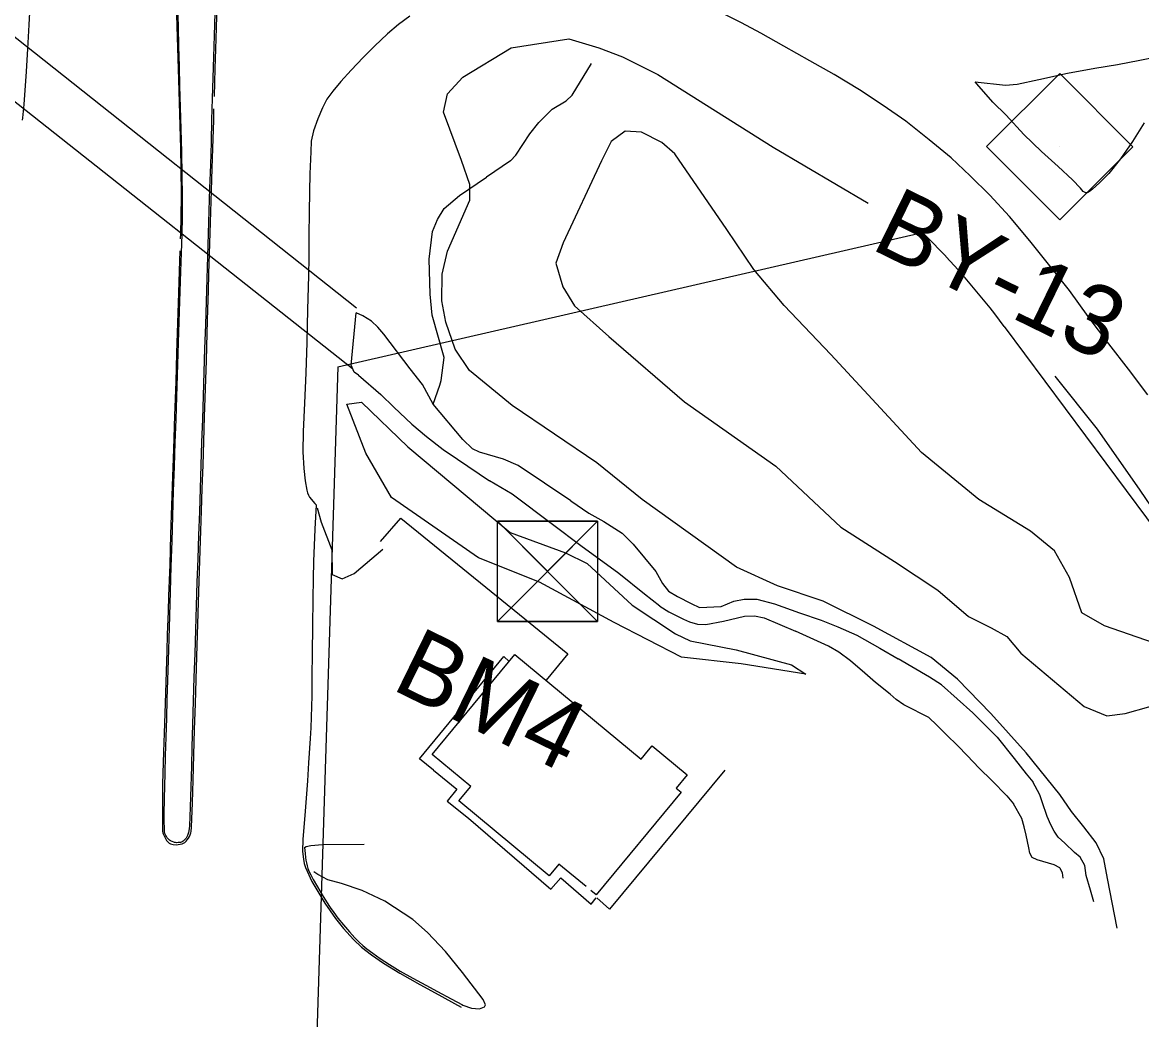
# Model space of a CAD drawing. Extents: x 1517485 to 1521905, y 636528 to 640355.
# Drawn here: x 1520407.4 to 1520728.2, y 637499.4 to 637785.1 of the extents above; entities that cross this region are included whole.
import ezdxf

# ---------------------------------------------------------------- set-up
doc = ezdxf.new("R2010")
doc.units = 0
for name, color, linetype in [('CTL Secondary Horizontal and Vertical CELL', 7, 'Continuous'), ('CTL Secondary Horizontal and Vertical Text', 7, 'Continuous'), ('CTL Vertical Benchmark CELL', 7, 'Continuous'), ('CTL Vertical Benchmark Text', 7, 'Continuous'), ('Exist Building', 7, 'Continuous'), ('Exist Hydro Stream or Body of Water', 7, 'Continuous'), ('Exist Right of Way Line', 7, 'Continuous'), ('Exist Roads Curbs', 7, 'Continuous'), ('Exist Roads EOP', 7, 'Continuous'), ('Exist Roads EOP Other', 7, 'Continuous'), ('Exist Structure Major Deck Tunnel Box Culvert', 7, 'Continuous'), ('Exist Vegetation Woods Line', 7, 'Continuous')]:
    doc.layers.add(name, color=color, linetype=linetype)

msp = doc.modelspace()

# ---------------------------------------------------------------- linework, layer by layer
at = {"layer": 'CTL Secondary Horizontal and Vertical CELL'}
msp.add_line((1520704.64, 637749.42), (1520704.64, 637749.42), dxfattribs=at)
msp.add_lwpolyline([(1520683.78, 637749.49), (1520704.75, 637770.45), (1520725.75, 637749.45), (1520704.78, 637728.49)], close=True, dxfattribs=at)
at = {"layer": 'CTL Vertical Benchmark CELL'}
msp.add_line((1520557.94, 637627.84), (1520557.94, 637627.84), dxfattribs=at)
msp.add_lwpolyline([(1520543.53, 637642.19), (1520572.28, 637642.19), (1520572.28, 637613.44), (1520543.53, 637613.44)], close=True, dxfattribs=at)
for points in [[(1520572.28, 637642.19), (1520543.53, 637613.44), (1520557.91, 637627.82), (1520572.28, 637613.44), (1520543.53, 637642.19)], [(1520557.91, 637627.82), (1520572.28, 637642.19), (1520543.53, 637642.19), (1520557.91, 637627.82)], [(1520557.91, 637627.82), (1520543.53, 637613.44), (1520572.28, 637613.44), (1520557.91, 637627.82)]]:
    msp.add_lwpolyline(points, dxfattribs=at)
at = {"layer": 'Exist Building'}
msp.add_lwpolyline([(1520568.97, 637537.55), (1520561.18, 637543.99), (1520558.42, 637540.66), (1520532.52, 637562.09), (1520535.92, 637566.2), (1520524.87, 637575.34), (1520548.59, 637604.03), (1520584.8, 637574.07), (1520586.89, 637576.6), (1520587.95, 637577.87), (1520597.98, 637569.58), (1520594.79, 637565.73), (1520596.18, 637564.58), (1520571.84, 637535.17), (1520570.36, 637536.4)], dxfattribs=at)
at = {"layer": 'Exist Hydro Stream or Body of Water'}
for p, q in [((1520527.4, 637682.47), (1520528.31, 637689.09)), ((1520503.75, 637684.08), (1520502.48, 637684.94)), ((1520638.49, 637606.43), (1520628.97, 637610.67)), ((1520695.12, 637569.8), (1520697, 637567.51)), ((1520689.56, 637563.5), (1520691.52, 637561.25))]:
    msp.add_line(p, q, dxfattribs=at)
for points in [[(1520548.79, 637747.01), (1520552.84, 637753.14), (1520555.46, 637756.46), (1520559.2, 637760.27), (1520563.29, 637762.6), (1520564.94, 637764.28), (1520570.49, 637773.36)], [(1520548.79, 637747.01), (1520547.28, 637745.43), (1520540.43, 637740.72)], [(1520528.31, 637689.09), (1520524.87, 637701.21), (1520524.29, 637707.26), (1520524.03, 637717.24), (1520524.96, 637725.22), (1520526.35, 637728.66), (1520528.31, 637731.8), (1520532.66, 637735.53), (1520540.43, 637740.72)], [(1520502.48, 637684.94), (1520501.67, 637686.86), (1520503.05, 637701.87)], [(1520564.57, 637648.08), (1520549.48, 637658.12), (1520545.25, 637659.97), (1520538.4, 637661.96), (1520536.42, 637662.95), (1520533.63, 637665.59), (1520525.18, 637675.68), (1520522.06, 637681.35), (1520518.54, 637685.81), (1520510.98, 637695.81), (1520509.24, 637697.82), (1520507.42, 637699.51), (1520505, 637701.02), (1520503.05, 637701.87)], [(1520503.75, 637684.08), (1520510.09, 637678.47), (1520513.86, 637674.89), (1520518.99, 637669.95), (1520523.19, 637666.45), (1520527.98, 637662.74), (1520532.07, 637659.94), (1520541.32, 637653.79)], [(1520525.18, 637675.68), (1520527.05, 637681.16), (1520527.4, 637682.47)], [(1520559.38, 637641.23), (1520547.77, 637649.91), (1520541.32, 637653.79)], [(1520564.57, 637648.08), (1520569.75, 637644.54), (1520574.09, 637642.1), (1520579.33, 637638.74), (1520582.45, 637635.61), (1520588.96, 637627.84), (1520590.91, 637624.34), (1520592.57, 637622.18), (1520595.13, 637620.62), (1520599.13, 637618.65), (1520601.47, 637617.52), (1520607.65, 637617.75), (1520611.35, 637619.26), (1520614.24, 637619.9), (1520617.93, 637619.87), (1520622.97, 637618.52), (1520630.1, 637615.96)], [(1520590.08, 637617.84), (1520585.69, 637621.27), (1520578.32, 637627.26), (1520567.49, 637635.11), (1520559.38, 637641.23)], [(1520590.08, 637617.84), (1520592.72, 637616.22), (1520596.94, 637614.15), (1520598.62, 637613.34)], [(1520630.1, 637615.96), (1520636.35, 637613.89), (1520641.1, 637611.98)], [(1520598.62, 637613.34), (1520600.93, 637612.66), (1520603.26, 637612.65), (1520608.35, 637613.58), (1520614.38, 637614.97), (1520617.21, 637615.12), (1520619.98, 637614.51), (1520628.97, 637610.67)], [(1520641.1, 637611.98), (1520646.63, 637609.52), (1520653.16, 637605.79), (1520658.41, 637602.76)], [(1520651.9, 637595.96), (1520648.85, 637598.7), (1520644.73, 637602.24), (1520641.38, 637604.72), (1520638.49, 637606.43)], [(1520670.89, 637595.28), (1520667.46, 637597.56), (1520658.41, 637602.76)], [(1520689.56, 637563.5), (1520685.24, 637567.88), (1520681.63, 637571.46), (1520678.19, 637575.08), (1520675.54, 637577.86), (1520672.19, 637581.13), (1520669.56, 637583.74), (1520667.22, 637585.94), (1520665.09, 637587.04), (1520662.54, 637588.31), (1520660.02, 637589.62), (1520657.82, 637591.16), (1520656.11, 637592.66), (1520651.9, 637595.96)], [(1520670.89, 637595.28), (1520679.79, 637587.32), (1520686.82, 637580.33), (1520691.72, 637574.25), (1520695.12, 637569.8)], [(1520710.61, 637545.98), (1520709, 637547.33), (1520706.17, 637550), (1520704.33, 637551.65), (1520703.11, 637553.4), (1520702.16, 637555.22), (1520701.15, 637557.64), (1520699.75, 637561.78), (1520699.02, 637563.85), (1520697, 637567.51)], [(1520704.84, 637542.75), (1520704.73, 637542.94), (1520703.18, 637543.79), (1520698.3, 637545.16), (1520696.84, 637545.89), (1520696.14, 637547.09), (1520695.86, 637548.61), (1520695.1, 637552.3), (1520694.59, 637554.67), (1520693.91, 637557.03), (1520691.52, 637561.25)], [(1520712.32, 637540.72), (1520711.97, 637543.57), (1520710.61, 637545.98)], [(1520705.75, 637539.9), (1520705.56, 637541.46), (1520704.84, 637542.75)], [(1520714.54, 637533.17), (1520713.61, 637536.49), (1520712.32, 637540.72)]]:
    msp.add_lwpolyline(points, dxfattribs=at)
at = {"layer": 'Exist Right of Way Line'}
for p, q in [((1520497.8, 637686.45), (1520665.43, 637724.89)), ((1520688.84, 637698), (1520778.77, 637576.91)), ((1520497.8, 637686.45), (1520477.57, 637046.61))]:
    msp.add_line(p, q, dxfattribs=at)
msp.add_arc((1520504.19, 637560.87), 230, 36.6002, 45.4902, dxfattribs=at)
at = {"layer": 'Exist Roads Curbs'}
for points in [[(1520462.51, 637787.75), (1520462.33, 637781.38), (1520462.15, 637775.21), (1520461.98, 637769.24), (1520461.81, 637763.28), (1520461.63, 637757.13), (1520461.45, 637750.78), (1520461.26, 637744.24), (1520461.06, 637737.64), (1520460.86, 637731.08), (1520460.66, 637724.58), (1520460.46, 637718.13), (1520460.26, 637711.66), (1520460.05, 637705.09), (1520459.84, 637698.42), (1520459.63, 637691.64), (1520459.42, 637684.85), (1520459.2, 637678.12), (1520458.99, 637671.44), (1520458.77, 637664.82), (1520458.56, 637658.21), (1520458.34, 637651.57), (1520458.11, 637644.9), (1520457.88, 637638.19), (1520457.66, 637631.46), (1520457.43, 637624.7), (1520457.21, 637617.92), (1520456.99, 637611.11), (1520456.77, 637604.31), (1520456.56, 637597.51), (1520456.36, 637590.74), (1520456.16, 637583.97), (1520455.98, 637577.61), (1520455.82, 637572.02), (1520455.58, 637563.2), (1520455.42, 637557.53), (1520455.31, 637555.01), (1520455.18, 637554.05), (1520454.98, 637553.04), (1520454.69, 637552.13), (1520454.51, 637551.75), (1520454.32, 637551.43), (1520453.88, 637550.92), (1520453.66, 637550.71), (1520453.42, 637550.54), (1520453.19, 637550.4), (1520452.96, 637550.29), (1520452.73, 637550.21), (1520452.51, 637550.16), (1520452.05, 637550.12), (1520451.54, 637550.11), (1520451.28, 637550.14), (1520451.03, 637550.18), (1520450.77, 637550.25), (1520450.29, 637550.45), (1520449.88, 637550.64), (1520449.56, 637550.82), (1520449.41, 637550.93), (1520449.13, 637551.22), (1520448.88, 637551.54), (1520448.65, 637551.86), (1520448.47, 637552.19), (1520448.31, 637552.56), (1520448.24, 637552.76), (1520448.16, 637553.23), (1520448.12, 637553.82), (1520448.09, 637554.61), (1520448.05, 637555.8), (1520448.05, 637558.35), (1520448.1, 637562.64), (1520448.27, 637570.02), (1520448.42, 637574.96), (1520448.58, 637580.33), (1520448.74, 637585.74), (1520448.9, 637591.19), (1520449.06, 637596.68), (1520449.22, 637602.39), (1520449.41, 637608.53), (1520449.61, 637615.09), (1520449.83, 637622.07), (1520450.05, 637629.26), (1520450.28, 637636.45), (1520450.51, 637643.63), (1520450.74, 637650.8), (1520450.97, 637657.87), (1520451.2, 637664.73), (1520451.42, 637671.37), (1520451.63, 637677.8), (1520451.84, 637684.07), (1520452.05, 637690.24), (1520452.25, 637696.31), (1520452.45, 637702.28), (1520452.64, 637708.09), (1520452.82, 637713.7), (1520452.99, 637719.11), (1520453.14, 637724.32), (1520453.24, 637729.62), (1520453.27, 637735.33), (1520453.21, 637741.43), (1520453.07, 637747.94), (1520452.89, 637754.51), (1520452.72, 637760.8), (1520452.55, 637766.83), (1520452.39, 637772.58), (1520452.24, 637778.22), (1520452.09, 637783.92), (1520451.94, 637789.67)], [(1520488.26, 637548.73), (1520488.41, 637546.97), (1520488.55, 637545.86), (1520488.67, 637545.07), (1520488.81, 637544.3), (1520488.99, 637543.5), (1520489.24, 637542.67), (1520489.59, 637541.8), (1520490.03, 637540.9), (1520490.77, 637539.58), (1520491.99, 637537.46), (1520493.35, 637535.14), (1520494.53, 637533.21), (1520495.59, 637531.57), (1520496.63, 637530.11), (1520497.85, 637528.53), (1520499.47, 637526.56), (1520501.17, 637524.55), (1520502.67, 637522.89), (1520503.94, 637521.59), (1520504.98, 637520.66), (1520506.14, 637519.73), (1520507.81, 637518.46), (1520509.97, 637516.92), (1520512.58, 637515.22), (1520515.69, 637513.34), (1520519.32, 637511.28), (1520523.04, 637509.25), (1520526.4, 637507.44), (1520530.32, 637505.36), (1520533.53, 637503.66)], [(1520533.35, 637503.76), (1520533.64, 637503.59), (1520536.11, 637502.68), (1520538.37, 637502.5), (1520539.81, 637503.05), (1520540.12, 637503.68), (1520539.49, 637505.19), (1520533.53, 637512.94), (1520528.69, 637518.98), (1520523.5, 637524.36), (1520519.27, 637528.09), (1520511.26, 637533.31), (1520504.75, 637536.41), (1520498.9, 637538.37), (1520494.92, 637539.5), (1520492.03, 637540.96), (1520490.88, 637541.79)]]:
    msp.add_lwpolyline(points, dxfattribs=at)
at = {"layer": 'Exist Roads EOP'}
for points in [[(1520407.37, 637757.09), (1520407.5, 637757.78), (1520407.89, 637761.53), (1520408.54, 637771.04), (1520408.96, 637777.5), (1520409.36, 637784.43), (1520409.72, 637791.52), (1520409.99, 637798.46), (1520410.2, 637804.97), (1520410.39, 637810.8), (1520410.76, 637820.38), (1520412.34, 637824.12), (1520412.72, 637825.48), (1520412.93, 637826.93), (1520412.95, 637832.19), (1520412.3, 637840.96), (1520411.15, 637849.53), (1520409.62, 637857.38), (1520407.7, 637865.28), (1520405.99, 637870.96)], [(1520462.44, 637763.87), (1520462.68, 637771.84), (1520462.85, 637777.4), (1520463.03, 637783.49), (1520463.25, 637790.21)], [(1520451.59, 637787.24), (1520451.76, 637780.84), (1520451.95, 637774.76), (1520452.13, 637768.66), (1520452.31, 637762.18), (1520452.48, 637755.55), (1520452.67, 637749.01), (1520452.83, 637743.26), (1520452.94, 637735.56), (1520452.8, 637729.33), (1520452.67, 637724.62), (1520452.65, 637723.07)], [(1520518.47, 637786.85), (1520515.23, 637784.47), (1520512.03, 637781.82), (1520508.3, 637778.27), (1520505.04, 637775.02), (1520501.64, 637771.36), (1520498.7, 637768.2), (1520496.34, 637765.43), (1520494.66, 637763.06), (1520493.41, 637760.61), (1520492.11, 637757.49), (1520490.87, 637754.03), (1520490.2, 637751.07), (1520490.02, 637747.99), (1520489.8, 637741.69), (1520489.67, 637736.6), (1520489.57, 637730.59), (1520489.52, 637724.11), (1520489.48, 637717.84), (1520489.37, 637712.45), (1520489.09, 637702.83), (1520488.87, 637693.38), (1520488.66, 637684.7), (1520488.28, 637675.99), (1520487.86, 637667.85), (1520487.73, 637662.1), (1520488.04, 637657.26), (1520488.4, 637653.76), (1520488.9, 637651.06), (1520489.12, 637650.29), (1520489.4, 637649.62), (1520489.72, 637649.04), (1520491.21, 637647.3), (1520491.57, 637646.9), (1520491.22, 637639.9), (1520490.8, 637630.63), (1520490.71, 637625.81), (1520490.63, 637619.86), (1520490.53, 637612.19), (1520490.43, 637604.33), (1520490.38, 637597.84), (1520490.31, 637592.22), (1520490.05, 637583.03), (1520489.85, 637579.91), (1520489.38, 637572.98), (1520489.08, 637567.8), (1520488.37, 637557.85), (1520487.77, 637551.16), (1520487.67, 637547.62), (1520487.94, 637545.37), (1520488.18, 637544.18), (1520488.54, 637542.97), (1520490.37, 637539.02), (1520494.08, 637532.8), (1520497.09, 637528.36), (1520499.45, 637525.51), (1520502.27, 637522.38), (1520504.6, 637520.19), (1520507.45, 637518.01), (1520510.89, 637515.64), (1520515.59, 637512.73), (1520521.31, 637509.48), (1520525.67, 637507.1), (1520533.18, 637503.01)], [(1520730.01, 637678.42), (1520724.43, 637685.72), (1520718.8, 637693.02), (1520712.86, 637700.87), (1520707.57, 637708.24), (1520701.91, 637715.4), (1520696.21, 637722.56), (1520690.38, 637729.44), (1520684.7, 637735.63), (1520679.06, 637741.13), (1520673.62, 637746.27), (1520667.36, 637751.43), (1520660.6, 637756.76), (1520654.17, 637761.27), (1520647.31, 637765.77), (1520640.04, 637770.17), (1520633.1, 637774.07), (1520625.66, 637778.3), (1520619.11, 637781.96), (1520613.49, 637784.95), (1520607.96, 637787.7)], [(1520728.99, 637756.29), (1520725.65, 637750.96), (1520722.19, 637745.99), (1520718.79, 637741.84), (1520716.15, 637739.12), (1520714.13, 637737.31), (1520713.26, 637736.6), (1520712.85, 637736.38), (1520712.63, 637736.3), (1520712.42, 637736.28), (1520712.21, 637736.3), (1520712, 637736.37), (1520711.81, 637736.47), (1520711.63, 637736.57), (1520711.48, 637736.69), (1520710.67, 637737.6), (1520708.39, 637739.98), (1520704.29, 637743.82), (1520699.52, 637748.14), (1520694.49, 637753.02), (1520689.35, 637758.47), (1520685.53, 637762.28), (1520680.96, 637767.49), (1520680.54, 637768.03), (1520689.21, 637767.11), (1520692.58, 637767.4), (1520698.76, 637768.73), (1520707, 637770.57), (1520714.78, 637771.99), (1520721.26, 637773.03), (1520727.72, 637774.3), (1520733.85, 637775.5)], [(1520452.55, 637719.66), (1520452.36, 637713.83), (1520452.05, 637704.69), (1520451.87, 637699.07), (1520451.6, 637690.32), (1520451.35, 637682.17), (1520451.02, 637672.5), (1520450.69, 637662.84), (1520450.45, 637654.99), (1520450.16, 637646.7), (1520449.88, 637638.37), (1520449.6, 637629.66), (1520449.29, 637620.83), (1520449.13, 637616.29), (1520448.91, 637609.71), (1520448.75, 637604.93), (1520448.57, 637599.14), (1520448.37, 637592.99), (1520448.19, 637587.11), (1520448, 637581.49), (1520447.83, 637576.14), (1520447.59, 637566.9), (1520447.53, 637560.03), (1520447.57, 637553.82), (1520447.59, 637553.33), (1520447.65, 637552.95), (1520447.74, 637552.61), (1520448.09, 637551.84), (1520448.71, 637550.77), (1520449.09, 637550.33), (1520449.28, 637550.15), (1520449.48, 637550), (1520449.67, 637549.89), (1520449.87, 637549.81), (1520450.6, 637549.63), (1520451.48, 637549.53), (1520452.04, 637549.55), (1520452.63, 637549.65), (1520453.17, 637549.8), (1520453.38, 637549.88), (1520453.57, 637549.98), (1520453.91, 637550.21), (1520454.29, 637550.54), (1520454.65, 637550.94), (1520454.97, 637551.39), (1520455.24, 637551.87), (1520455.47, 637552.39), (1520455.64, 637552.9), (1520455.74, 637553.36), (1520455.85, 637554.52), (1520456.1, 637561.5), (1520456.3, 637568.05), (1520456.52, 637575.18), (1520456.74, 637582.56), (1520456.97, 637589.86), (1520457.18, 637596.88), (1520457.39, 637603.41), (1520457.58, 637609.66), (1520457.78, 637615.89), (1520457.98, 637622.02), (1520458.18, 637628.03), (1520458.37, 637633.85), (1520458.56, 637639.43), (1520458.75, 637645.19), (1520458.96, 637651.55), (1520459.17, 637658.25), (1520459.39, 637665.02), (1520459.63, 637672.2), (1520459.88, 637680.14), (1520460.13, 637688.28), (1520460.36, 637696.09), (1520460.55, 637702.94), (1520460.69, 637708.23), (1520460.83, 637713.13), (1520461.02, 637718.8), (1520461.23, 637724.84), (1520461.43, 637730.85), (1520461.61, 637736.94), (1520461.79, 637743.24), (1520461.96, 637748.99), (1520462.22, 637757.04), (1520462.29, 637760.37)]]:
    msp.add_lwpolyline(points, dxfattribs=at)
at = {"layer": 'Exist Roads EOP Other'}
for points in [[(1520491.88, 637646.06), (1520493.04, 637641.95), (1520496.11, 637634.04), (1520496.19, 637626.9), (1520499.09, 637625.71), (1520502.51, 637627.25), (1520510.72, 637634.19)], [(1520510.08, 637636.4), (1520515.89, 637643.07), (1520551.38, 637614.23), (1520563.71, 637604.2), (1520557.52, 637596.64)], [(1520525.22, 637570.86), (1520521.17, 637574.16), (1520545.35, 637603.45), (1520546.95, 637602.05)], [(1520525.22, 637570.86), (1520531.88, 637565.41), (1520529.16, 637562.05), (1520535.25, 637557.12), (1520558.86, 637536.81), (1520561.7, 637540.07), (1520570.4, 637532.51), (1520571.85, 637534.33)], [(1520608.73, 637570.84), (1520575.64, 637531.04), (1520572.05, 637534.29)], [(1520488.26, 637548.73), (1520488.7, 637549.01), (1520490.09, 637549.34), (1520493.4, 637549.61), (1520505.34, 637549.65)]]:
    msp.add_lwpolyline(points, dxfattribs=at)
at = {"layer": 'Exist Structure Major Deck Tunnel Box Culvert'}
for p, q in [((1520400.15, 637784.86), (1520503.18, 637703.34)), ((1520502.02, 637685.84), (1520399.79, 637766.57))]:
    msp.add_line(p, q, dxfattribs=at)
at = {"layer": 'Exist Vegetation Woods Line'}
for points in [[(1520695.12, 637575.85), (1520684.99, 637587.13), (1520675.45, 637596.95), (1520667.86, 637603.11), (1520651.4, 637612.15), (1520636.91, 637619.29), (1520623.84, 637623.64), (1520612.04, 637629.08), (1520585.07, 637648.42), (1520572.01, 637658.92), (1520547.81, 637675.36), (1520535.53, 637685.33), (1520531.42, 637691.46), (1520528.78, 637699.21), (1520527.57, 637705.3), (1520527.68, 637712.92), (1520529.27, 637719.58), (1520535.66, 637734.18), (1520535.61, 637738.62), (1520533.21, 637745.56), (1520528.06, 637759.36), (1520529.25, 637764.65), (1520533.67, 637769.36), (1520547.5, 637777.83), (1520564.04, 637780.36), (1520572.63, 637777.82), (1520579.39, 637775.21), (1520589.58, 637770.21), (1520622.62, 637749.37), (1520649.82, 637733.31)], [(1520717.56, 637612.22), (1520711.12, 637615.99), (1520707.59, 637626.09), (1520703.2, 637633.67), (1520696.41, 637639.31), (1520681.53, 637648.4), (1520665.08, 637661.85), (1520649.82, 637678.37), (1520639.11, 637689.94), (1520625.75, 637703.95), (1520617.02, 637714.26), (1520609.34, 637725.79), (1520594.42, 637747.39), (1520590.72, 637750.68), (1520584.86, 637753.62), (1520580.16, 637753.93), (1520576.19, 637751), (1520573.43, 637745.42), (1520562.37, 637721.9), (1520560.31, 637716.13), (1520562.35, 637709.29), (1520565.65, 637703.94), (1520575.5, 637695.07), (1520597.18, 637676.35), (1520623.34, 637657.95)], [(1520703.36, 637683.76), (1520715.5, 637668.59), (1520727.69, 637651.08), (1520732.36, 637644.24)], [(1520613.47, 637601.34), (1520596.28, 637603.22), (1520576.99, 637613.18), (1520555.66, 637624.7), (1520538.1, 637631.74), (1520513.16, 637648.96), (1520505.82, 637661.69), (1520500.43, 637675.72), (1520504.55, 637676.3)], [(1520504.55, 637676.3), (1520517.88, 637663.55), (1520547.25, 637639.01), (1520563.05, 637633.12), (1520569.24, 637630.05), (1520582.18, 637618.18), (1520594.56, 637609.98), (1520598.8, 637607.9), (1520611.95, 637605.32), (1520627.85, 637601.09), (1520632.01, 637598.36), (1520613.47, 637601.34)], [(1520623.34, 637657.95), (1520641.95, 637640.5), (1520657.35, 637630.63), (1520669.85, 637622.44), (1520678.55, 637614.9), (1520685.11, 637611.7), (1520689.57, 637609.13), (1520693.55, 637604.44), (1520711.72, 637589.12)], [(1520711.72, 637589.12), (1520718.21, 637586.45), (1520723.47, 637587.08), (1520730.33, 637589.07), (1520736.33, 637591.15), (1520739.68, 637595.8), (1520740.74, 637601.07), (1520736.33, 637605.74), (1520717.56, 637612.22)], [(1520721.19, 637525.59), (1520718.45, 637539.88), (1520717.41, 637545.47), (1520715.18, 637550.04), (1520711.68, 637554.68), (1520708.11, 637559.03), (1520704.81, 637563.91), (1520695.12, 637575.85)]]:
    msp.add_lwpolyline(points, dxfattribs=at)

# ---------------------------------------------------------------- texts
at = {"layer": 'CTL Secondary Horizontal and Vertical Text'}
msp.add_text('BY-13', height=20, rotation=333.9377, dxfattribs=at).set_placement((1520650.14, 637720.42))
at = {"layer": 'CTL Vertical Benchmark Text'}
msp.add_text('BM4', height=20, rotation=333.9377, dxfattribs=at).set_placement((1520512.77, 637594.27))

doc.saveas('drawing.dxf')
